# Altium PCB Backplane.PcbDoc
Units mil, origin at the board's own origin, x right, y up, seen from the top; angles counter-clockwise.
Board outline 6520 x 1500 mil, 6 copper layers (Top Layer, DGND, +5V, AGND, VCC, Bottom Layer), stack 62 mil thick; 22 components, 85 nets, 235 pads, 4 vias.
Unrouted connection lines stored in the file: 32.
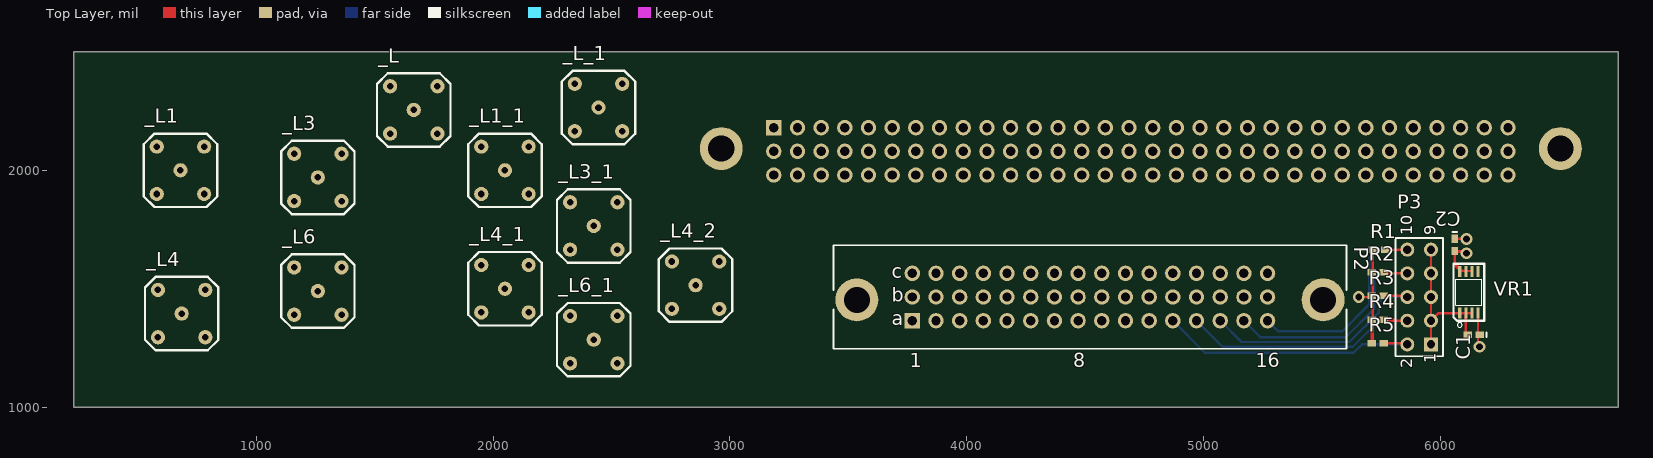
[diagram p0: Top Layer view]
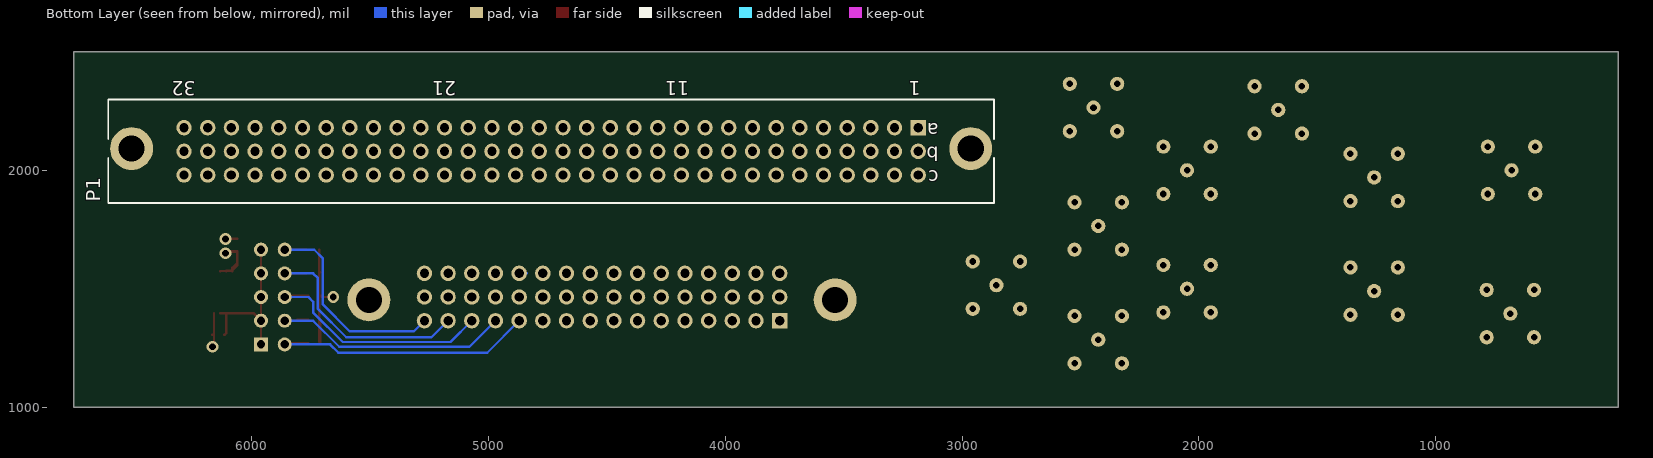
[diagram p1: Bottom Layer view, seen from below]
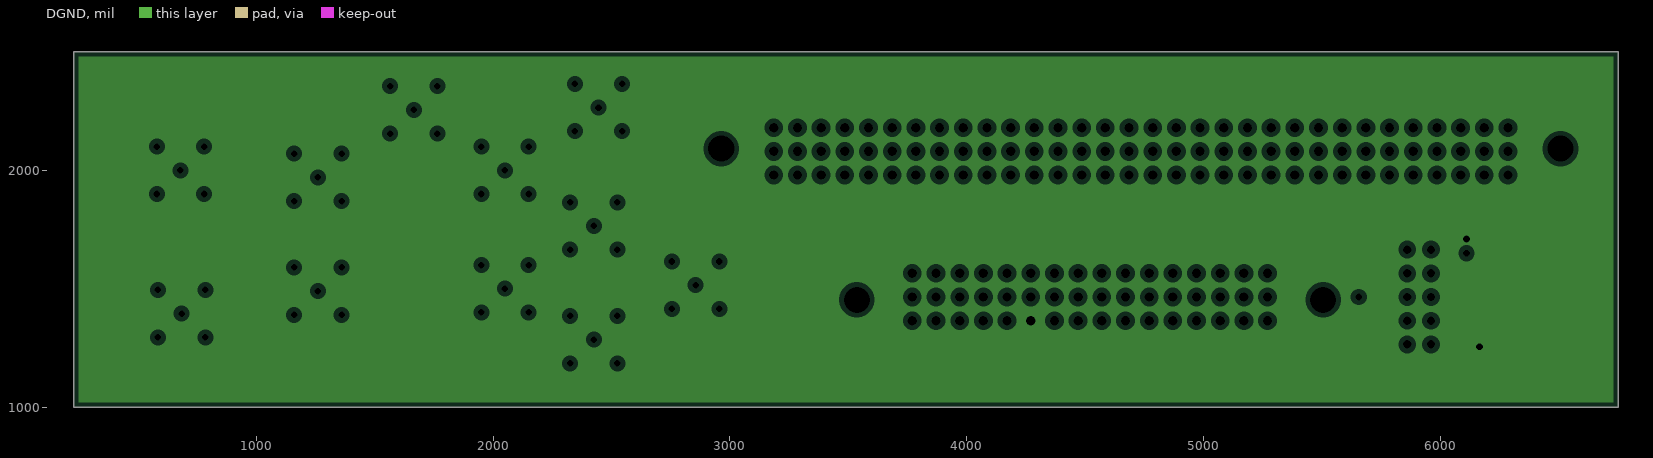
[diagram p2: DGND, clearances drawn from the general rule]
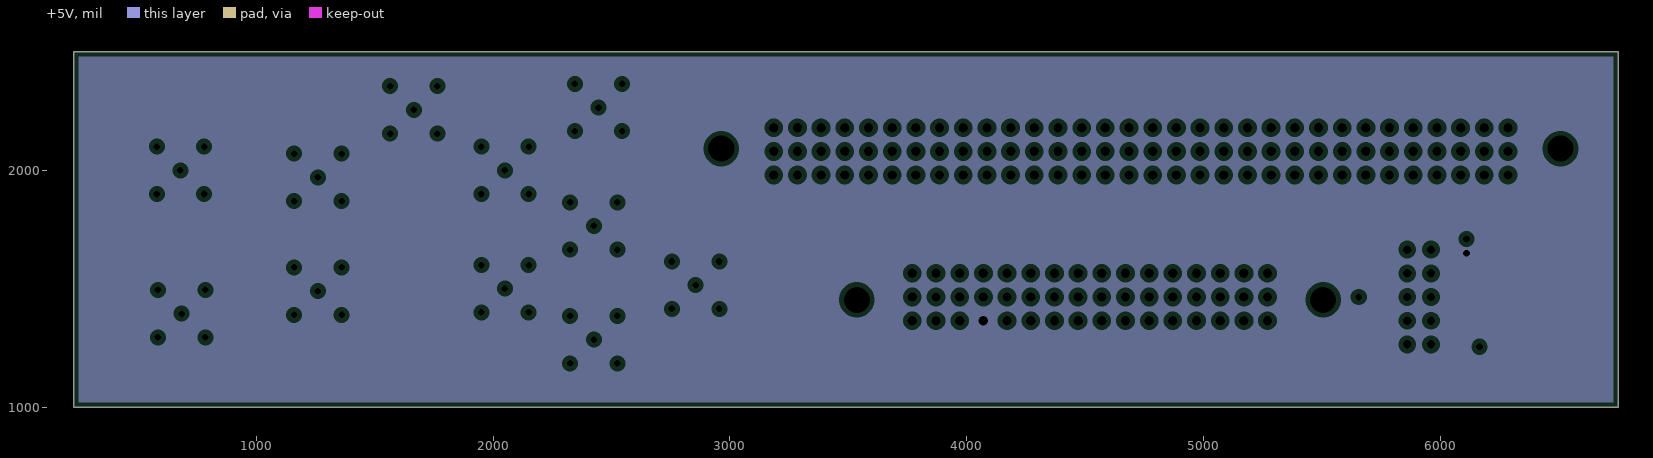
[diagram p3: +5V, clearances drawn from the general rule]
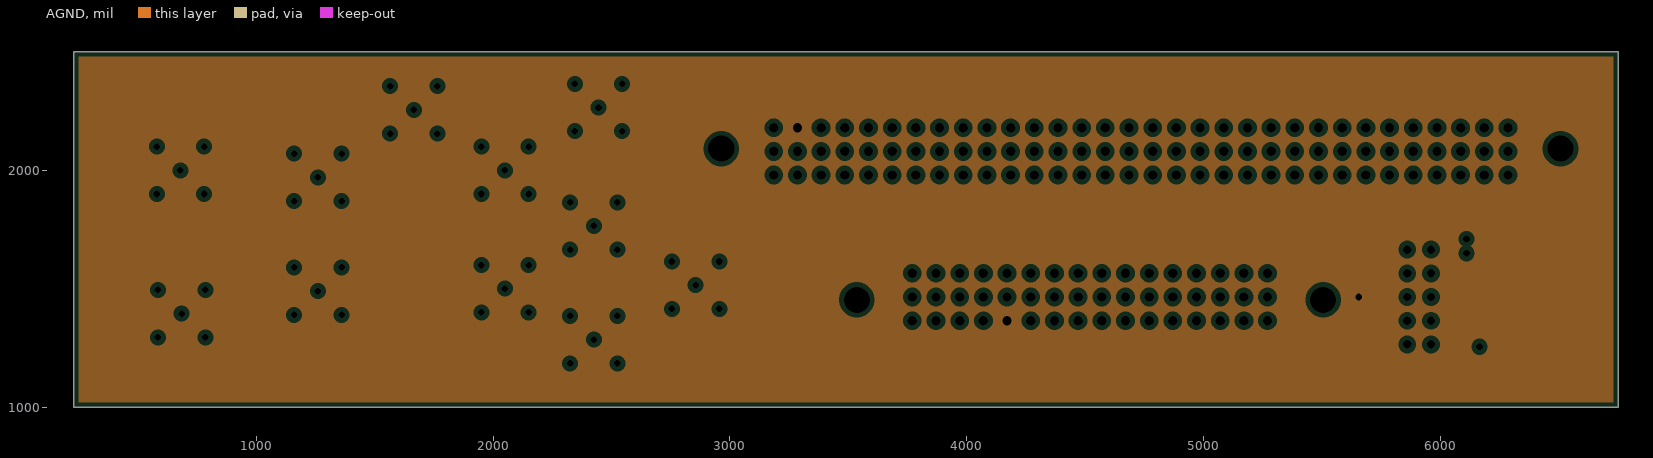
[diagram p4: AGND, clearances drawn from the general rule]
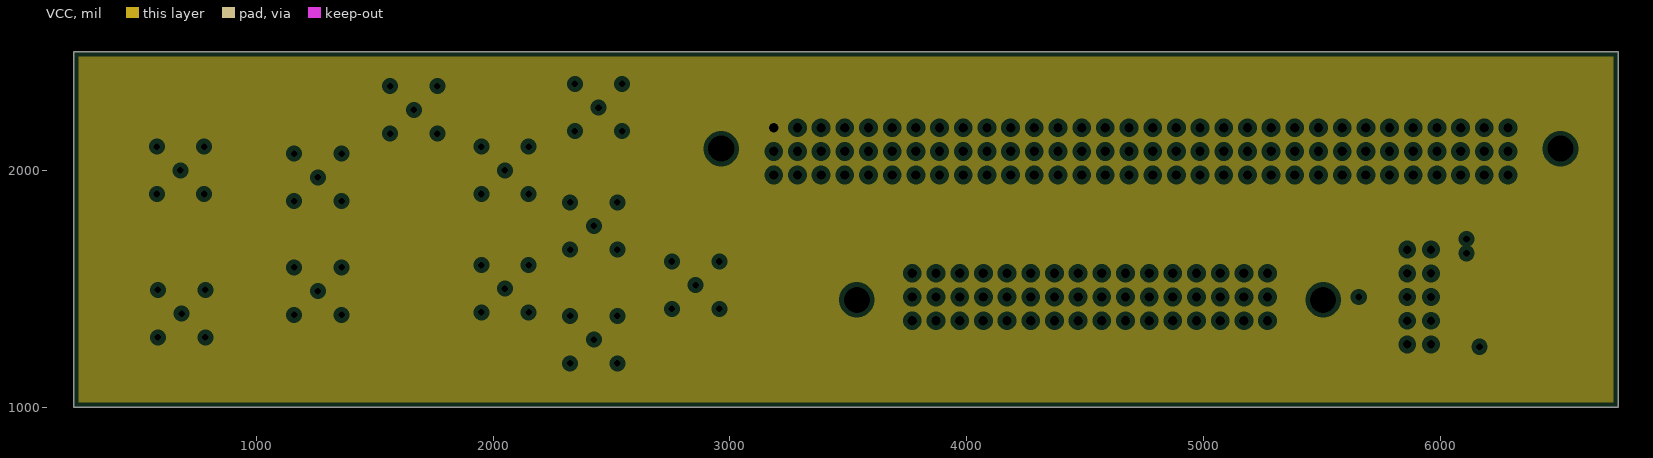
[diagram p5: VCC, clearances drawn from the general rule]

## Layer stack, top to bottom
Top Layer: signal copper 1.4
Dielectric: prepreg 10.72, FR-4, Dk 4.8
DGND: plane copper 1.4, net DGND
Dielectric: core 10.72, FR-4, Dk 4.8
+5V: plane copper 1.4, net +5V
Dielectric: prepreg 10.72, FR-4, Dk 4.8
AGND: plane copper 1.4, net AGND
Dielectric: core 10.72, FR-4, Dk 4.8
VCC: plane copper 1.4, net VCC
Dielectric: prepreg 10.72, FR-4, Dk 4.8
Bottom Layer: signal copper 1.4

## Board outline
230,1000 6750,1000 6750,2500 230,2500

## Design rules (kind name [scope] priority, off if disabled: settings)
Clearance [All] p1: gap=10
ComponentClearance [All] p1: gap=10 collisioncheckmode=3 verticalgap=10
PlaneClearance [All] p1: clearance=20
PlaneConnect [All] p1: planeconnectstyle=Relief reliefexpansion=20 reliefentries=4 reliefconductorwidth=10 reliefairgap=10
PolygonConnect [All] p1: connectstyle=Relief reliefconductorwidth=10 reliefentries=4 polygonreliefangle="90 Angle"
RoomDefinition "Digital Connector" [InComponentClass('Digital Connector')] p1: confinementstyle=ConfineIn formatcopy=TRUE lockcomponents=FALSE outline 3175,1140 6600,1140 6600,1950 3175,1950
RoomDefinition "Analog Connector" [InComponentClass('Analog Connector')] p2: confinementstyle=ConfineIn formatcopy=TRUE lockcomponents=FALSE outline 2655,1760 6675,1760 6675,2435 2655,2435
RoutingVias [All] p1: holewidth=28 width=50 viastyle="Through Hole" minholewidth=28 minwidth=50 maxholewidth=28 maxwidth=50
SolderMaskExpansion [All] p1: expansion=4
SupplyNets VCC [OnLayer('VCC')] p1: voltage=10.00
SupplyNets +5V [OnLayer('+5V')] p2: voltage=5.000
SupplyNets DGND [OnLayer(DGND)] p3: voltage=0.000
SupplyNets AGND [OnLayer('AGND')] p4: voltage=0.000
TestPointUsage [All] p1: valid=0 allowmultiple=FALSE
Testpoint [All] p1: side=15 testpointundercomponent=TRUE minsize=40 maxsize=100 preferedsize=60 minholesize=0 maxholesize=40 preferedholesize=32 testpointgrid=1 style=1023 order=0-112345678
Width [InNet('SIPMOUT1')] p1: maxlimit=17.39 minlimit=6.35 preferedwidth=17.39 impedancedriven=TRUE minimp=50.000000 maximp=80.000000 favimp=50.000000
16 further rules are at their usual default settings.

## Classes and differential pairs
component class "Analog Connector": P1
component class "Digital Connector": C1 C2 P2 P3 R1 R2 R3 R4 R5 R? VR1

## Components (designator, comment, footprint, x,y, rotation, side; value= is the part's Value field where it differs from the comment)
_L "Comment" "LEMO EPA.00" 1665,2255 r0 top
_L1 "Comment" "LEMO EPA.00" 680,2000 r0 top
_L1_1 "Comment" "LEMO EPA.00" 2050,2000 r0 top
_L3 "Comment" "LEMO EPA.00" 1260,1970 r0 top
_L3_1 "Comment" "LEMO EPA.00" 2425,1765 r0 top
_L4 "Comment" "LEMO EPA.00" 685,1395 r0 top
_L4_1 "Comment" "LEMO EPA.00" 2050,1500 r0 top
_L4_2 "Comment" "LEMO EPA.00" 2855,1515 r0 top
_L6 "Comment" "LEMO EPA.00" 1260,1490 r0 top
_L6_1 "Comment" "LEMO EPA.00" 2425,1285 r0 top
_L_1 "Comment" "LEMO EPA.00" 2445,2265 r0 top
C1 "Kemet C1206C106K9PACTU" 0402 6140,1305 r180 top
C2 "Kemet C0402C104K8PACTU" 0402 6060,1685 r270 top
P1 "DIN41612 96 pin, Backplane" EURO2.54-2V96 4735,2080 r0 bottom
P2 "DIN41612 48 pin, Backplane" EURO2.54-2V48 4520,1465 r0 top
P3 "Header 5X2" HDR2X5 5960,1265 r90 top
R1 "Res2" 1005[0402] 5740,1665 r0 top
R2 "Res2" 1005[0402] 5735,1570 r0 top
R3 "Res2" 1005[0402] 5735,1470 r0 top
R4 "Res2" 1005[0402] 5735,1370 r0 top
R5 "Res2" 1005[0402] 5735,1270 r0 top
VR1 "Kemet C0402C102K5RACTU" RM-8 6120,1485 r0 top

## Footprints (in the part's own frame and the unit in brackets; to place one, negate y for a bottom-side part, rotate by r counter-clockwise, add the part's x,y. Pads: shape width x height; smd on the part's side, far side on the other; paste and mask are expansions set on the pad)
0402 [mm] "Chip Capacitor; Body 1.0 x 0.5 mm (LxW typ)"
  rect 0.9x0.7 smd: 1(-0.65,0) 2(0.65,0)
  silkscreen extent -1.4,-0.25 -1.4,0.25
1005[0402] [mm] "Chip Resistor; Body 1.1 x 0.5 mm (LxW typ)"
  rect 0.9x0.7 smd: 1(-0.65,0) 2(0.65,0)
EURO2.54-2V48 [mm] "Connector; DIN 41612, Type 2C, Thru-Hole; Rows a+b+c, 48 Position; Vertical"
  round 4.6 hole 2.8: 17(-25,-0.3) 18(25,-0.3)
  rect 1.65x1.65 hole 1: A1(-19.05,-2.54)
  round 1.65 hole 1: A2(-16.51,-2.54) A3(-13.97,-2.54) A4(-11.43,-2.54) A5(-8.89,-2.54) A6(-6.35,-2.54) A7(-3.81,-2.54) A8(-1.27,-2.54) A9(1.27,-2.54) A10(3.81,-2.54) A11(6.35,-2.54) A12(8.89,-2.54) A13(11.43,-2.54) A14(13.97,-2.54) A15(16.51,-2.54) A16(19.05,-2.54) B1(-19.05,0) B2(-16.51,0) B3(-13.97,0) B4(-11.43,0) B5(-8.89,0) B6(-6.35,0) B7(-3.81,0) B8(-1.27,0) B9(1.27,0) B10(3.81,0) B11(6.35,0) B12(8.89,0) B13(11.43,0) B14(13.97,0) B15(16.51,0) B16(19.05,0) C1(-19.05,2.54) C2(-16.51,2.54) C3(-13.97,2.54) C4(-11.43,2.54) C5(-8.89,2.54) C6(-6.35,2.54) C7(-3.81,2.54) C8(-1.27,2.54) C9(1.27,2.54) C10(3.81,2.54) C11(6.35,2.54) C12(8.89,2.54) C13(11.43,2.54) C14(13.97,2.54) C15(16.51,2.54) C16(19.05,2.54)
  silkscreen extent -27.5,-5.55 27.5,5.55
EURO2.54-2V96 [mm] "Connector; DIN 41612, Type C, Thru-Hole; Rows a+b+c, 96 Position; Vertical"
  round 4.6 hole 2.8: 33(-45,-0.3) 34(45,-0.3)
  rect 1.65x1.65 hole 1: A1(-39.37,-2.54)
  round 1.65 hole 1: A2(-36.83,-2.54) A3(-34.29,-2.54) A4(-31.75,-2.54) A5(-29.21,-2.54) A6(-26.67,-2.54) A7(-24.13,-2.54) A8(-21.59,-2.54) A9(-19.05,-2.54) A10(-16.51,-2.54) A11(-13.97,-2.54) A12(-11.43,-2.54) A13(-8.89,-2.54) A14(-6.35,-2.54) A15(-3.81,-2.54) A16(-1.27,-2.54) A17(1.27,-2.54) A18(3.81,-2.54) A19(6.35,-2.54) A20(8.89,-2.54) A21(11.43,-2.54) A22(13.97,-2.54) A23(16.51,-2.54) A24(19.05,-2.54) A25(21.59,-2.54) A26(24.13,-2.54) A27(26.67,-2.54) A28(29.21,-2.54) A29(31.75,-2.54) A30(34.29,-2.54) A31(36.83,-2.54) A32(39.37,-2.54) B1(-39.37,0) B2(-36.83,0) B3(-34.29,0) B4(-31.75,0) B5(-29.21,0) B6(-26.67,0) B7(-24.13,0) B8(-21.59,0) B9(-19.05,0) B10(-16.51,0) B11(-13.97,0) B12(-11.43,0) B13(-8.89,0) B14(-6.35,0) B15(-3.81,0) B16(-1.27,0) B17(1.27,0) B18(3.81,0) B19(6.35,0) B20(8.89,0) B21(11.43,0) B22(13.97,0) B23(16.51,0) B24(19.05,0) B25(21.59,0) B26(24.13,0) B27(26.67,0) B28(29.21,0) B29(31.75,0) B30(34.29,0) B31(36.83,0) B32(39.37,0) C1(-39.37,2.54) C2(-36.83,2.54) C3(-34.29,2.54) C4(-31.75,2.54) C5(-29.21,2.54) C6(-26.67,2.54) C7(-24.13,2.54) C8(-21.59,2.54) C9(-19.05,2.54) C10(-16.51,2.54) C11(-13.97,2.54) C12(-11.43,2.54) C13(-8.89,2.54) C14(-6.35,2.54) C15(-3.81,2.54) C16(-1.27,2.54) C17(1.27,2.54) C18(3.81,2.54) C19(6.35,2.54) C20(8.89,2.54) C21(11.43,2.54) C22(13.97,2.54) C23(16.51,2.54) C24(19.05,2.54) C25(21.59,2.54) C26(24.13,2.54) C27(26.67,2.54) C28(29.21,2.54) C29(31.75,2.54) C30(34.29,2.54) C31(36.83,2.54) C32(39.37,2.54)
  silkscreen extent -47.5,-5.55 47.5,5.55
HDR2X5 [mm] "Connector; Header; 5x2 Position"
  rect 1.5x1.5 hole 0.9: 1(0,0)
  round 1.5 hole 0.9: 2(0,2.54) 3(2.54,0) 4(2.54,2.54) 5(5.08,0) 6(5.08,2.54) 7(7.62,0) 8(7.62,2.54) 9(10.16,0) 10(10.16,2.54)
  silkscreen extent -1.27,-1.27 11.43,3.81
"LEMO EPA.00" [mil]
  round 60 hole 27.56: 0(0,0) 1(-100,100) 2(100,100) 3(100,-100) 4(-100,-100)
  silkscreen extent -155,-155 155,155
RM-8 [mil]
  rect 13.4x46.9 smd: 1(-38.6,-87.8) 2(-12.6,-87.8) 3(12.6,-87.8) 4(38.6,-87.8) 5(38.6,87.8) 6(12.6,87.8) 7(-12.6,87.8) 8(-38.6,87.8)
  silkscreen extent -65,-148 65,121

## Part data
C1 C2: library part Cap, "Capacitor"
P3: "Header, 5-Pin, Dual row"
R1 R2 R3 R4 R5: "Resistor"
VR1: library part ADP3335

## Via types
v1: diameter 50, hole 28, Top Layer to Bottom Layer, 4 vias

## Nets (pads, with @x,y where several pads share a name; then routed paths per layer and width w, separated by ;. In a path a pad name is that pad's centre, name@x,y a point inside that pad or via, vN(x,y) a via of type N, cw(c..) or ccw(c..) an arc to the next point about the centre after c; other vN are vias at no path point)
+3.3V: C1.2 P3.1 P3.3 P3.5 P3.7 P3.9 VR1.1 VR1.2 VR1.3 | length 870.2
  Top Layer w10: P3.9 P3.7 P3.5 P3.1 P3.3 5992.2,1397.2 ; VR1.1 5992.2,1397.2 ; C1.2 6107.4,1312.01 VR1.2 ; VR1.3 VR1.2 ; 5992.2,1397.2 VR1.2
+5V: C2.2 P2.A4 VR1.6 VR1.7 VR1.8 | length 519.2
  Top Layer w10: VR1.7 VR1.7@6107.4,1575 ; v1(6110,1650) v1@6105,1655 ; VR1.6 VR1.6@6132.6,1575 ; C2.2@6060,1655 v1@6105,1655 ; C2.2@6060,1655 C2.2 6100.59,1659.41 v1@6105,1655 ; C2.2@6060,1655 v1@6105,1655 ; C2.2@6060,1655 6060,1598.6 VR1.8@6081.4,1577.2 ; C2.2@6060,1655 6060,1609.4 6081.4,1588 VR1.8@6081.4,1577.2 ; VR1.8@6081.4,1576 VR1.8@6082.6,1576 ; VR1.8@6081.4,1576 VR1.8@6082.6,1576 ; VR1.8@6081.4,1576 VR1.8 VR1.8@6081.4,1577.2 ; VR1.8@6081.4,1577.2 VR1.8@6082.6,1576 ; VR1.8@6082.6,1576 VR1.8@6083.6,1575 ; VR1.8@6082.6,1576 VR1.7@6107.4,1576 ; VR1.8@6082.6,1576 VR1.7@6107.4,1576 ; VR1.8@6082.6,1576 VR1.8@6083.6,1575 ; VR1.8@6083.6,1575 VR1.7@6107.4,1575 ; VR1.8@6083.6,1575 VR1.7@6107.4,1575 ; v1@6105,1655 v1@6110,1655 ; v1@6105,1655 v1@6110,1655 ; VR1.7@6107.4,1575 VR1.6@6132.6,1575 ; VR1.7@6107.4,1575 VR1.6@6132.6,1575 ; VR1.7@6107.4,1575 VR1.7@6107.4,1576 ; v1@6110,1655 6120,1655 v1@6110,1655
+210V: P2.A2
-5V: P2.A3
ADC_EXT1: P2.A7
ADC_EXT2: P2.A8
AGND: P1.A2 P2.A5 R1.1 R2.1 R3.1 R4.1 R5.1 | length 1568.6
  Top Layer w10: v1(5655,1465) R3.1@5704.41,1465 ; R5.1 R5.1@5710,1270 ; R4.1 R4.1@5710,1370 ; R3.1@5704.41,1465 R3.1@5704.41,1470 ; R3.1@5704.41,1465 R3.1@5704.41,1470 ; R3.1@5704.41,1470 R3.1 ; R3.1 R3.1@5714,1470 ; R3.1 R3.1@5714,1470 ; R5.1@5710,1270 R4.1@5710,1370 ; R5.1@5710,1270 R4.1@5710,1370 ; R4.1@5710,1370 R4.1@5714.41,1370 ; R4.1@5710,1370 R4.1@5714.41,1370 ; R3.1@5714,1470 R2.1@5714,1570 ; R3.1@5714,1470 R2.1@5714,1570 ; R2.1@5714,1570 R2.1 R2.1@5714,1570 ; R2.1@5714,1570 R2.1@5714.41,1570 ; R2.1@5714,1570 R2.1@5714.41,1570 ; R5.1@5714.41,1275 R4.1@5714.41,1370 ; R5.1@5714.41,1275 R2.1@5714.41,1570 ; R5.1@5714.41,1275 R3.1@5714.41,1470 ; R4.1@5714.41,1370 R3.1@5714.41,1470 ; R4.1@5714.41,1370 R3.1@5714.41,1470 ; R3.1@5714.41,1470 R2.1@5714.41,1570 ; R2.1@5714.41,1570 R1.1 R2.1@5714.41,1570
CP2201/LA: P2.A1
DGND: C1.1 C2.1 P2.A6 VR1.4 | length 388.5
  Top Layer w10: C2.1 6109.41,1710.59 v1(6110,1710) ; v1(6165,1255) v1@6158.6,1261.4 ; v1@6158.6,1261.4 C1.1@6158.6,1305 ; v1@6158.6,1261.4 6158.6,1325 VR1.4 C1.1@6158.6,1305 ; v1@6158.6,1261.4 C1.1@6158.6,1305 ; C1.1@6158.6,1305 C1.1 C1.1@6158.6,1305
ID0: P2.A16 P3.10 R1.2 | length 960.2
  Top Layer w10: R1.2 P3.10
  Bottom Layer w10: P2.A16 5315,1320 5585,1320 5700,1435 5700,1630 5735,1665 P3.10
ID1: P2.A15 P3.8 R2.2 | length 1047.8
  Top Layer w10: 5812,1565 5765.59,1565 P3.8
  Bottom Layer w10: P2.A15 5240,1295 5600,1295 5720,1415 5720,1545 5740,1565 P3.8
ID2: P2.A14 P3.6 R3.2 | length 1136.2
  Top Layer w10: P3.6 P3.6@5860,1470 ; P3.6@5860,1470 R3.2 P3.6@5860,1470
  Bottom Layer w10: P2.A14 5160,1275 5615,1275 5740,1400 5740,1445 5760,1465 P3.6
ID3: P2.A13 P3.4 R4.2 | length 1129
  Top Layer w10: R4.2 5807,1370 5812,1365 ; R4.2@5765.59,1365 5812,1365 ; P3.4 5812,1365
  Bottom Layer w10: P2.A13 5080,1255 5630,1255 5740,1365 P3.4
ID4: P2.A12 P3.2 R5.2 | length 1264.2
  Top Layer w10: P3.2 P3.2@5860,1270 ; P3.2@5860,1270 R5.2 P3.2@5860,1270
  Bottom Layer w10: P2.A12 5005,1230 5633.28,1230 5668.28,1265 P3.2
SIPMBIAS1: P1.B1 P2.C1
SIPMBIAS2: P1.B2 P2.B1
SIPMBIAS3: P1.B3 P2.C2
SIPMBIAS4: P1.B4 P2.B2
SIPMBIAS5: P1.B5 P2.C3
SIPMBIAS6: P1.B6 P2.B3
SIPMBIAS7: P1.B7 P2.C4
SIPMBIAS8: P1.B8 P2.B4
SIPMBIAS9: P1.B9 P2.C5
SIPMBIAS10: P1.B10 P2.B5
SIPMBIAS11: P1.B11 P2.C6
SIPMBIAS12: P1.B12 P2.B6
SIPMBIAS13: P1.B13 P2.C7
SIPMBIAS14: P1.B14 P2.B7
SIPMBIAS15: P1.B15 P2.C8
SIPMBIAS16: P1.B16 P2.B8
SIPMBIAS17: P1.B17 P2.C9
SIPMBIAS18: P1.B18 P2.B9
SIPMBIAS19: P1.B19 P2.C10
SIPMBIAS20: P1.B20 P2.B10
SIPMBIAS21: P1.B21 P2.C11
SIPMBIAS22: P1.B22 P2.B11
SIPMBIAS23: P1.B23 P2.C12 | length 32.9
  Bottom Layer w10: 4837.15,1565 P2.C12
SIPMBIAS24: P1.B24 P2.B12
SIPMBIAS25: P1.B25 P2.C13
SIPMBIAS26: P1.B26 P2.B13
SIPMBIAS27: P1.B27 P2.C14
SIPMBIAS28: P1.B28 P2.B14
SIPMBIAS29: P1.B29 P2.C15
SIPMBIAS30: P1.B30 P2.B15
SIPMBIAS31: P1.B31 P2.C16
SIPMBIAS32: P1.B32 P2.B16
SIPMOUT1: P1.C1
SIPMOUT2: P1.C2
SIPMOUT3: P1.C3
SIPMOUT4: P1.C4
SIPMOUT5: P1.C5
SIPMOUT6: P1.C6
SIPMOUT7: P1.C7
SIPMOUT8: P1.C8
SIPMOUT9: P1.C9
SIPMOUT10: P1.C10
SIPMOUT11: P1.C11
SIPMOUT12: P1.C12
SIPMOUT13: P1.C13
SIPMOUT14: P1.C14
SIPMOUT15: P1.C15
SIPMOUT16: P1.C16
SIPMOUT17: P1.C17
SIPMOUT18: P1.C18
SIPMOUT19: P1.C19
SIPMOUT20: P1.C20
SIPMOUT21: P1.C21
SIPMOUT22: P1.C22
SIPMOUT23: P1.C23
SIPMOUT24: P1.C24
SIPMOUT25: P1.C25
SIPMOUT26: P1.C26
SIPMOUT27: P1.C27
SIPMOUT28: P1.C28
SIPMOUT29: P1.C29
SIPMOUT30: P1.C30
SIPMOUT31: P1.C31
SIPMOUT32: P1.C32
SUMMED1: P1.A5
SUMMED2: P1.A8
SUMMED3: P1.A13
SUMMED4: P1.A19
SUMMED5: P1.A24
SUMMED6: P1.A32
VCC: P1.A1
pads on no net: _L1.0 _L1.1 _L1.2 _L1.3 _L1.4 _L1_1.0 _L1_1.1 _L1_1.2 _L1_1.3 _L1_1.4 _L3.0 _L3.1 _L3.2 _L3.3 _L3.4 _L3_1.0 _L3_1.1 _L3_1.2 _L3_1.3 _L3_1.4 _L4.0 _L4.1 _L4.2 _L4.3 _L4.4 _L4_1.0 _L4_1.1 _L4_1.2 _L4_1.3 _L4_1.4 _L4_2.0 _L4_2.1 _L4_2.2 _L4_2.3 _L4_2.4 _L6.0 _L6.1 _L6.2 _L6.3 _L6.4 _L6_1.0 _L6_1.1 _L6_1.2 _L6_1.3 _L6_1.4 _L.0 _L.1 _L.2 _L.3 _L.4 _L_1.0 _L_1.1 _L_1.2 _L_1.3 _L_1.4 P1.33 P1.34 P1.A3 P1.A4 P1.A6 P1.A7 P1.A9 P1.A10 P1.A11 P1.A12 P1.A14 P1.A15 P1.A16 P1.A17 P1.A18 P1.A20 P1.A21 P1.A22 P1.A23 P1.A25 P1.A26 P1.A27 P1.A28 P1.A29 P1.A30 P1.A31 P2.17 P2.18 P2.A9 P2.A10 P2.A11 VR1.5

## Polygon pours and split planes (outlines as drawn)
DGND on DGND (split plane): 6729.61,1020.39 250.39,1020.39 250.39,2479.61 6729.61,2479.61
AGND on AGND (split plane): 6729.61,1020.39 250.39,1020.39 250.39,2479.61 6729.61,2479.61
+5V on +5V (split plane): 6729.61,1020.39 250.39,1020.39 250.39,2479.61 6729.61,2479.61
VCC on VCC (split plane): 6729.61,1020.39 250.39,1020.39 250.39,2479.61 6729.61,2479.61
